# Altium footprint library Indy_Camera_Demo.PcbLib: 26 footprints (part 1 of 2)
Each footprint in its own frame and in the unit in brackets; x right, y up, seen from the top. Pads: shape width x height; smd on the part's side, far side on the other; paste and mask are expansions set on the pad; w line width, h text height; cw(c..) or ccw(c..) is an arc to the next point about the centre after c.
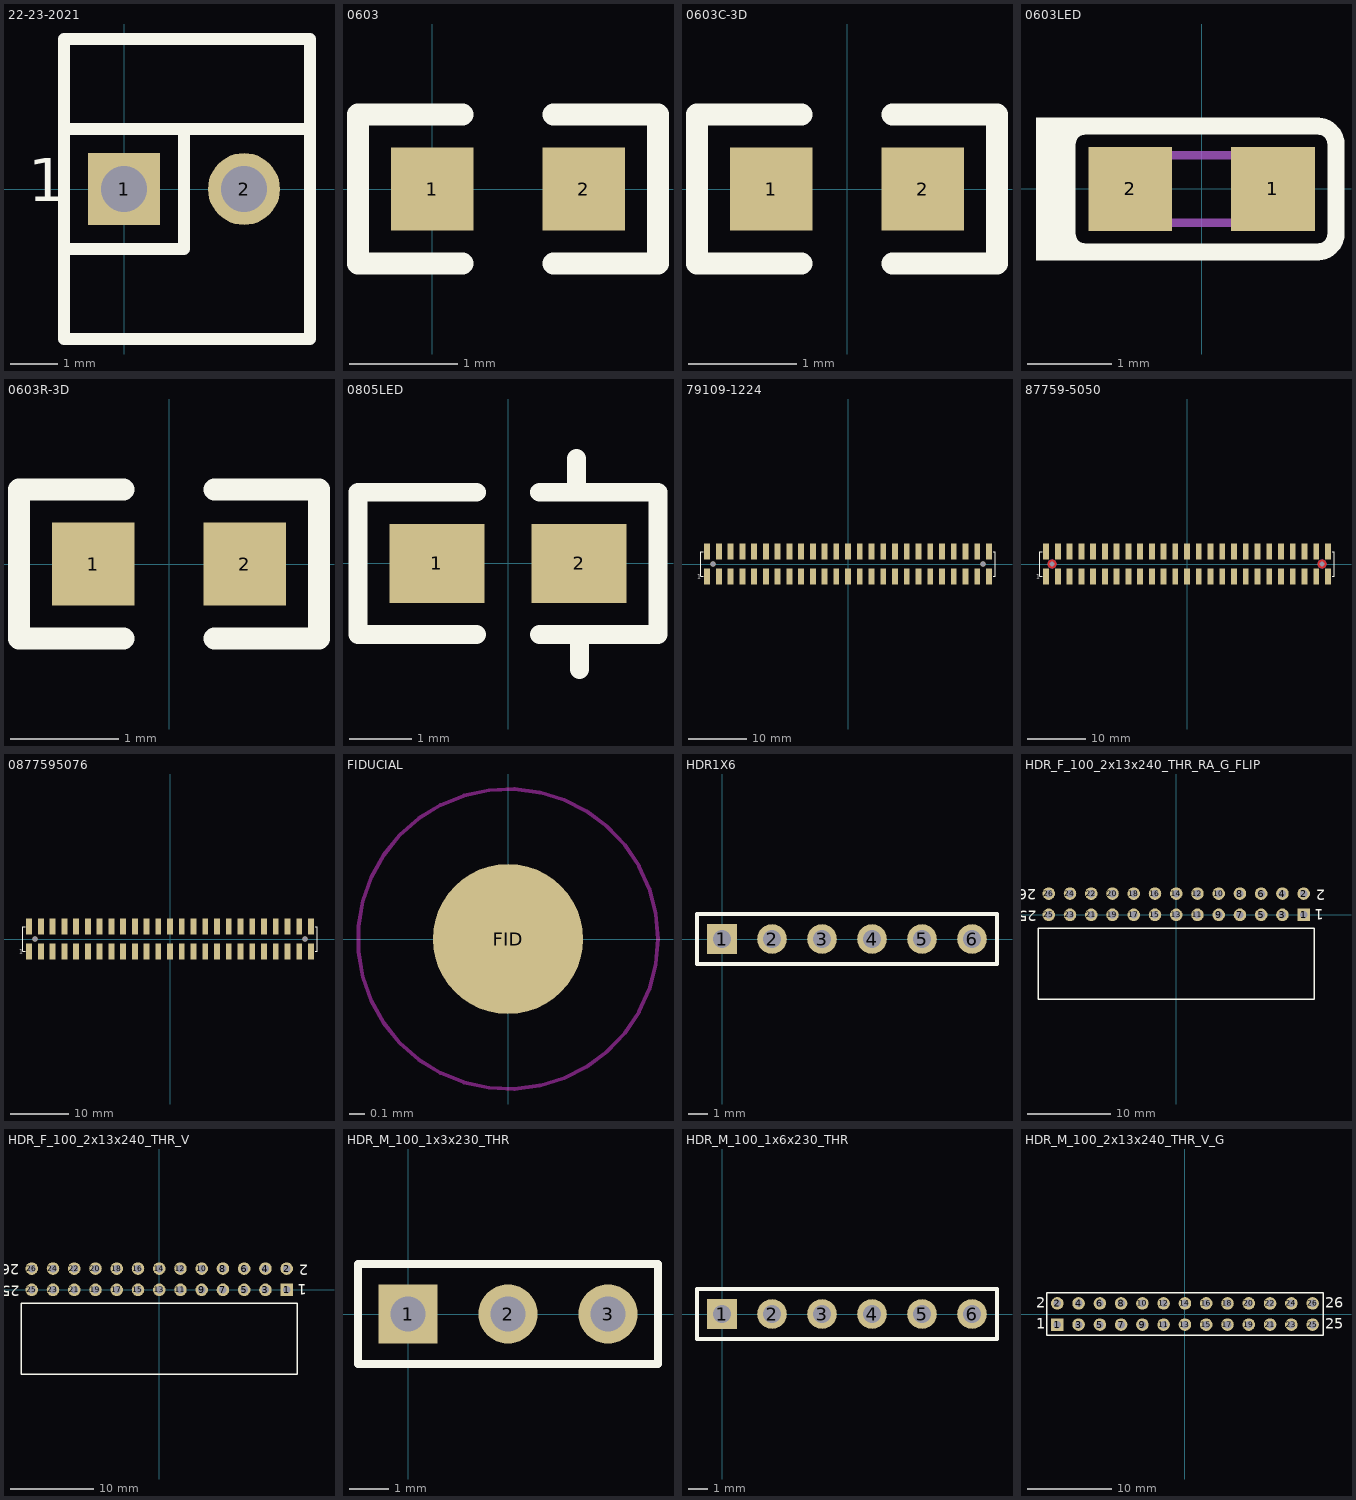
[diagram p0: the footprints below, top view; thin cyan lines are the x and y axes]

## 22-23-2021 [mil] "Molex Header, Straight-Friction-Lock, 1x2"
height 420
pads (2):
  rect 60x60 hole 38: 1(0,0)
  round 60 hole 38: 2(100,0)
Top Overlay:
  lines w10: -50,-50 50,-50 50,50 ; -50,50 155,50 ; -50,-125 -50,125 155,125 155,-125 -50,-125
  text "1" at -80,-10 h36

## 0603 [mil]
height 10
pads (2):
  rect 30x30 smd: 1(0,0) 2(55,0)
Top Overlay:
  lines w8: 11,-27 -27,-27 -27,27 11,27 ; 44,-27 82,-27 82,27 44,27
3D body: height 17.72, standoff 0, extent -4,-15.75 7.82,15.75
3D body: height 17.72, standoff 0, extent 7.82,-15.75 47.18,15.75
3D body: height 17.72, standoff 0, extent 47.18,-15.75 59,15.75

## 0603C-3D [mil]
height 17.72
pads (2):
  rect 30x30 smd: 1(-27.5,0) 2(27.5,0)
Top Overlay:
  lines w8: -16.5,-27 -54.5,-27 -54.5,27 -16.5,27 ; 16.5,-27 54.5,-27 54.5,27 16.5,27
3D body: height 17.72, standoff 0, extent -31.5,-15.75 -19.68,15.75
3D body: height 17.72, standoff 0, extent -19.68,-15.75 19.68,15.75
3D body: height 17.72, standoff 0, extent 19.68,-15.75 31.5,15.75

## 0603LED [mm]
pads (2):
  rect 1x1 smd: 1(0.85,0) 2(-0.85,0)
Top Overlay:
  rectangle: -1.782,0.665 -1.132,0.851
  rectangle: -1.973,-0.851 -1.515,0.851
  rectangle: -1.782,-0.851 -1.198,-0.686
  lines w0.203: -1.602,-0.533 ccw(c-1.386,-0.533) -1.386,-0.749 1.386,-0.749 ccw(c1.386,-0.533) 1.602,-0.533 1.602,0.533 ccw(c1.386,0.533) 1.386,0.749 -1.386,0.749 ccw(c-1.386,0.533) -1.602,0.533 -1.602,-0.533
Mechanical 7:
  lines w0.1: -0.8,-0.4 -0.8,0.4 0.8,0.4 0.8,-0.4 -0.8,-0.4
  text ".Comment" at -1.6,-0.9 h0.4
  text ".Designator" at -1.6,0.6 h0.4
3D body: height 0.46, standoff 0, extent -0.301,-0.464 0.493,0.402
3D body: height 0.38, standoff 0, extent -0.502,-0.533 0.668,0.533
3D body: height 0.38, standoff 0, extent -0.925,-0.535 -0.5,0.535
3D body: height 0.38, standoff 0, extent 0.664,-0.532 1.089,0.532

## 0603R-3D [mil]
height 17.72
pads (2):
  rect 30x30 smd: 1(-27.5,0) 2(27.5,0)
Top Overlay:
  lines w8: -16.5,-27 -54.5,-27 -54.5,27 -16.5,27 ; 16.5,-27 54.5,-27 54.5,27 16.5,27
3D body: height 17.72, standoff 0, extent -31.5,-15.75 -19.68,15.75
3D body: height 17.72, standoff 0, extent -19.68,-15.75 19.68,15.75
3D body: height 17.72, standoff 0, extent 19.68,-15.75 31.5,15.75

## 0805LED [mil]
pads (2):
  rect 60x50 smd: 1(-45,0) 2(45,0)
Top Overlay:
  lines w12: -20,-45 -95,-45 -95,45 -20,45 ; 20,-45 95,-45 95,45 20,45 ; 43.5,45 43.5,66.42 ; 45.15,-67.32 45.15,-45
3D body: height 20, standoff 0, extent -101,-73.32 101,72.42

## 79109-1224 [mm] "Female Receptacle, 2x25, 2mm Pitch"
height 4.648
pads (52):
  round 0.9 hole 0.9 unplated: 0(-23,0) 0(23,0)
  rect 1x2.75 smd: 1(-24,-2.125) 2(-24,2.125) 3(-22,-2.125) 4(-22,2.125) 5(-20,-2.125) 6(-20,2.125) 7(-18,-2.125) 8(-18,2.125) 9(-16,-2.125) 10(-16,2.125) 11(-14,-2.125) 12(-14,2.125) 13(-12,-2.125) 14(-12,2.125) 15(-10,-2.125) 16(-10,2.125) 17(-8,-2.125) 18(-8,2.125) 19(-6,-2.125) 20(-6,2.125) 21(-4,-2.125) 22(-4,2.125) 23(-2,-2.125) 24(-2,2.125) 25(0,-2.125) 26(0,2.125) 27(2,-2.125) 28(2,2.125) 29(4,-2.125) 30(4,2.125) 31(6,-2.125) 32(6,2.125) 33(8.003,-2.1) 34(8,2.125) 35(10,-2.125) 36(10,2.125) 37(12,-2.125) 38(12,2.125) 39(14,-2.125) 40(14,2.125) 41(16,-2.125) 42(16,2.125) 43(18,-2.125) 44(18,2.125) 45(20,-2.125) 46(20,2.125) 47(22,-2.125) 48(22,2.125) 49(24,-2.125) 50(24,2.125)
Top Overlay:
  lines w0.2: -25.1,-2.1 -25.1,2.1 -24.7,2.1 ; 24.7,-2.1 25.1,-2.1 25.1,2.1 24.7,2.1
  lines w0.203: -25.1,-2.1 -24.697,-2.1
  text "1" at -25.73,-2.54 h0.76
3D body: height 4.64, standoff -1.26, extent -25.095,-2.667 25.095,2.667

## 87759-5050 [mm] "Male Receptacle, 2x25, 2mm Pitch"
height 4.648
pads (52):
  round 0 hole 0.9 unplated: 0(-23,0) 0(23,0)
  rect 1x2.75 smd: 1(-24,-2.125) 2(-24,2.125) 3(-22,-2.125) 4(-22,2.125) 5(-20,-2.125) 6(-20,2.125) 7(-18,-2.125) 8(-18,2.125) 9(-16,-2.125) 10(-16,2.125) 11(-14,-2.125) 12(-14,2.125) 13(-12,-2.125) 14(-12,2.125) 15(-10,-2.125) 16(-10,2.125) 17(-8,-2.125) 18(-8,2.125) 19(-6,-2.125) 20(-6,2.125) 21(-4,-2.125) 22(-4,2.125) 23(-2,-2.125) 24(-2,2.125) 25(0,-2.125) 26(0,2.125) 27(2,-2.125) 28(2,2.125) 29(4,-2.125) 30(4,2.125) 31(6,-2.125) 32(6,2.125) 33(8.003,-2.1) 34(8,2.125) 35(10,-2.125) 36(10,2.125) 37(12,-2.125) 38(12,2.125) 39(14,-2.125) 40(14,2.125) 41(16,-2.125) 42(16,2.125) 43(18,-2.125) 44(18,2.125) 45(20,-2.125) 46(20,2.125) 47(22,-2.125) 48(22,2.125) 49(24,-2.125) 50(24,2.125)
Top Layer:
  pour cut-out: 22.231,0 22.257,-0.199 22.334,-0.384 22.456,-0.543 22.616,-0.666 22.801,-0.742 23,-0.769 23.199,-0.742 23.384,-0.666 23.543,-0.543 23.665,-0.384 23.742,-0.199 23.768,0 23.742,0.199 23.665,0.384 23.543,0.543 23.384,0.666 23.199,0.742 23,0.769 22.801,0.742 22.616,0.666 22.456,0.543 22.334,0.384 22.257,0.199
  pour cut-out: -23.769,0 -23.743,-0.199 -23.666,-0.384 -23.544,-0.543 -23.384,-0.666 -23.199,-0.742 -23,-0.769 -22.801,-0.742 -22.616,-0.666 -22.457,-0.543 -22.335,-0.384 -22.258,-0.199 -22.232,0 -22.258,0.199 -22.335,0.384 -22.457,0.543 -22.616,0.666 -22.801,0.742 -23,0.769 -23.199,0.742 -23.384,0.666 -23.544,0.543 -23.666,0.384 -23.743,0.199
Bottom Layer:
  pour cut-out: -23.769,0 -23.743,-0.199 -23.666,-0.384 -23.544,-0.543 -23.384,-0.666 -23.199,-0.742 -23,-0.769 -22.801,-0.742 -22.616,-0.666 -22.457,-0.543 -22.335,-0.384 -22.258,-0.199 -22.232,0 -22.258,0.199 -22.335,0.384 -22.457,0.543 -22.616,0.666 -22.801,0.742 -23,0.769 -23.199,0.742 -23.384,0.666 -23.544,0.543 -23.666,0.384 -23.743,0.199
  pour cut-out: 22.231,0 22.257,-0.199 22.334,-0.384 22.456,-0.543 22.616,-0.666 22.801,-0.742 23,-0.769 23.199,-0.742 23.384,-0.666 23.543,-0.543 23.665,-0.384 23.742,-0.199 23.768,0 23.742,0.199 23.665,0.384 23.543,0.543 23.384,0.666 23.199,0.742 23,0.769 22.801,0.742 22.616,0.666 22.456,0.543 22.334,0.384 22.257,0.199
Top Overlay:
  lines w0.2: -25.1,-2.1 -25.1,2.1 -24.7,2.1 ; 24.7,-2.1 25.1,-2.1 25.1,2.1 24.7,2.1
  lines w0.203: -25.1,-2.1 -24.697,-2.1
  text "1" at -25.73,-2.54 h0.76
3D body: height 6.48, standoff -1.52, extent -24.957,-2.75 24.943,2.75

## 0877595076 [mm] "Male Receptacle, 2x25, 2mm Pitch"
height 4.648
pads (52):
  round 0.9 hole 0.9 unplated: 0(-23,0) 0(23,0)
  rect 1x2.75 smd: 1(-24,-2.125) 2(-24,2.125) 3(-22,-2.125) 4(-22,2.125) 5(-20,-2.125) 6(-20,2.125) 7(-18,-2.125) 8(-18,2.125) 9(-16,-2.125) 10(-16,2.125) 11(-14,-2.125) 12(-14,2.125) 13(-12,-2.125) 14(-12,2.125) 15(-10,-2.125) 16(-10,2.125) 17(-8,-2.125) 18(-8,2.125) 19(-6,-2.125) 20(-6,2.125) 21(-4,-2.125) 22(-4,2.125) 23(-2,-2.125) 24(-2,2.125) 25(0,-2.125) 26(0,2.125) 27(2,-2.125) 28(2,2.125) 29(4,-2.125) 30(4,2.125) 31(6,-2.125) 32(6,2.125) 33(8.003,-2.1) 34(8,2.125) 35(10,-2.125) 36(10,2.125) 37(12,-2.125) 38(12,2.125) 39(14,-2.125) 40(14,2.125) 41(16,-2.125) 42(16,2.125) 43(18,-2.125) 44(18,2.125) 45(20,-2.125) 46(20,2.125) 47(22,-2.125) 48(22,2.125) 49(24,-2.125) 50(24,2.125)
Top Overlay:
  lines w0.2: -25.1,-2.1 -25.1,2.1 -24.7,2.1 ; 24.7,-2.1 25.1,-2.1 25.1,2.1 24.7,2.1
  lines w0.203: -25.1,-2.1 -24.697,-2.1
  text "1" at -25.73,-2.54 h0.76
3D body: height 4.64, standoff -1.26, extent -25.095,-2.667 25.095,2.667

## FIDUCIAL [mm] "Fiducial mark"
pads (1):
  round 1 smd paste-0.5 mask+0.5: FID(0,0)
Top Layer keep-out:
  circle w0.025: c0,0 r1

## HDR1X6 [mm] "Connector; Header; 6 Position"
pads (6):
  rect 1.5x1.5 hole 0.9: 1(0,0)
  round 1.5 hole 0.9: 2(2.54,0) 3(5.08,0) 4(7.62,0) 5(10.16,0) 6(12.7,0)
Top Overlay:
  lines w0.2: -1.27,-1.27 13.97,-1.27 13.97,1.27 -1.27,1.27 -1.27,-1.27

## HDR_F_100_2x13x240_THR_RA_G_FLIP [mm] "Connector; Header; 13x2 Position"
pads (26):
  rect 1.5x1.5 hole 0.9: 1(15.24,0)
  round 1.5 hole 0.9: 2(15.24,2.54) 3(12.7,0) 4(12.7,2.54) 5(10.16,0) 6(10.16,2.54) 7(7.62,0) 8(7.62,2.54) 9(5.08,0) 10(5.08,2.54) 11(2.54,0) 12(2.54,2.54) 13(0,0) 14(0,2.54) 15(-2.54,0) 16(-2.54,2.54) 17(-5.08,0) 18(-5.08,2.54) 19(-7.62,0) 20(-7.62,2.54) 21(-10.16,0) 22(-10.16,2.54) 23(-12.7,0) 24(-12.7,2.54) 25(-15.24,0) 26(-15.24,2.54)
Top Overlay:
  lines w0.2: -16.51,-10.1 -16.51,-1.6 16.51,-1.6 16.51,-10.1 -16.51,-10.1
  text "2" at 17.831,2.997 h1.27
  text "1" at 17.628,0.66 h1.27
  text "25" at -16.662,0.457 h1.27
  text "26" at -16.764,3.048 h1.27

## HDR_F_100_2x13x240_THR_V [mm] "Connector; Header; 13x2 Position"
pads (26):
  rect 1.5x1.5 hole 0.9: 1(15.24,0)
  round 1.5 hole 0.9: 2(15.24,2.54) 3(12.7,0) 4(12.7,2.54) 5(10.16,0) 6(10.16,2.54) 7(7.62,0) 8(7.62,2.54) 9(5.08,0) 10(5.08,2.54) 11(2.54,0) 12(2.54,2.54) 13(0,0) 14(0,2.54) 15(-2.54,0) 16(-2.54,2.54) 17(-5.08,0) 18(-5.08,2.54) 19(-7.62,0) 20(-7.62,2.54) 21(-10.16,0) 22(-10.16,2.54) 23(-12.7,0) 24(-12.7,2.54) 25(-15.24,0) 26(-15.24,2.54)
Top Overlay:
  lines w0.2: -16.51,-10.1 -16.51,-1.6 16.51,-1.6 16.51,-10.1 -16.51,-10.1
  text "2" at 17.831,2.997 h1.27
  text "1" at 17.628,0.66 h1.27
  text "25" at -16.662,0.457 h1.27
  text "26" at -16.764,3.048 h1.27

## HDR_M_100_1x3x230_THR [mm] "Connector; Header; 3 Position"
pads (3):
  rect 1.5x1.5 hole 0.9: 1(0,0)
  round 1.5 hole 0.9: 2(2.54,0) 3(5.08,0)
Top Overlay:
  lines w0.2: -1.27,-1.27 -1.27,1.27 6.35,1.27 6.35,-1.27 -1.27,-1.27

## HDR_M_100_1x6x230_THR [mm] "Connector; Header; 6 Position"
pads (6):
  rect 1.5x1.5 hole 0.9: 1(0,0)
  round 1.5 hole 0.9: 2(2.54,0) 3(5.08,0) 4(7.62,0) 5(10.16,0) 6(12.7,0)
Top Overlay:
  lines w0.2: -1.27,-1.27 13.97,-1.27 13.97,1.27 -1.27,1.27 -1.27,-1.27

## HDR_M_100_2x13x240_THR_V_G [mm] "Connector; Header; 13x2 Position"
pads (26):
  rect 1.5x1.5 hole 0.9: 1(-15.24,-1.27)
  round 1.5 hole 0.9: 2(-15.24,1.27) 3(-12.7,-1.27) 4(-12.7,1.27) 5(-10.16,-1.27) 6(-10.16,1.27) 7(-7.62,-1.27) 8(-7.62,1.27) 9(-5.08,-1.27) 10(-5.08,1.27) 11(-2.54,-1.27) 12(-2.54,1.27) 13(0,-1.27) 14(0,1.27) 15(2.54,-1.27) 16(2.54,1.27) 17(5.08,-1.27) 18(5.08,1.27) 19(7.62,-1.27) 20(7.62,1.27) 21(10.16,-1.27) 22(10.16,1.27) 23(12.7,-1.27) 24(12.7,1.27) 25(15.24,-1.27) 26(15.24,1.27)
Top Overlay:
  lines w0.2: -16.51,-2.54 16.51,-2.54 16.51,2.54 -16.51,2.54 -16.51,-2.54
  text "26" at 16.764,0.762 h1.27
  text "25" at 16.764,-1.778 h1.27
  text "1" at -17.78,-1.778 h1.27
  text "2" at -17.78,0.762 h1.27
